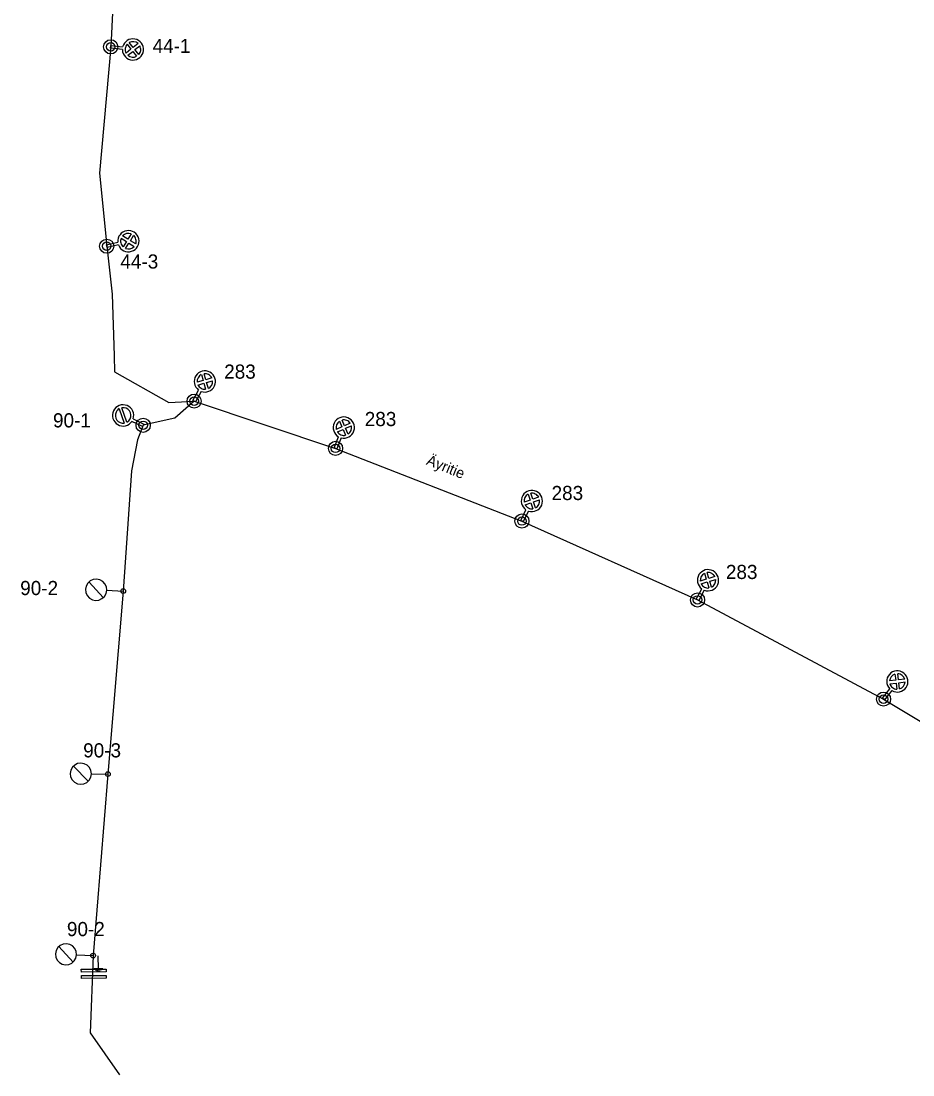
# Model space of a CAD drawing. Extents: x 25497851 to 25498523, y 6686544 to 6687372.
# Drawn here: x 25497924.4 to 25498113.5, y 6686887.2 to 6687110.6 of the extents above; entities that cross this region are included whole.
import ezdxf

# ---------------------------------------------------------------- set-up
doc = ezdxf.new("R2010")
doc.units = 0
for name, color, linetype in [('EL_CABLE_MAA', 7, 'Continuous'), ('KAAPELI', 7, 'Continuous'), ('KEYGWT_ANNOTATION', 7, 'Continuous'), ('Level 17', 7, 'Continuous'), ('Level 63', 7, 'Continuous'), ('MUU_UV-SUUNNITELMASYMBOLI', 7, 'Continuous'), ('PYLVAS', 7, 'Continuous'), ('Taso 1', 7, 'Continuous'), ('TEKSTI_SUUNNITELMA-ALUE', 7, 'Continuous'), ('VALAISIN', 7, 'Continuous')]:
    doc.layers.add(name, color=color, linetype=linetype)

msp = doc.modelspace()

# ---------------------------------------------------------------- linework, layer by layer
at = {"layer": 'EL_CABLE_MAA'}
for points in [[(25497946.1, 6686989.76), (25497942.85, 6686950.95)], [(25497942.85, 6686950.95), (25497939.72, 6686912.49)], [(25497939.72, 6686912.49), (25497939.1, 6686896.13), (25497945.31, 6686887.18)]]:
    msp.add_lwpolyline(points, dxfattribs=at)
at = {"layer": 'KAAPELI'}
for p, q in [((25497961.13, 6687030.03), (25497991.11, 6687020.01)), ((25497991.11, 6687020.01), (25498030.62, 6687004.6)), ((25498030.62, 6687004.6), (25498067.85, 6686987.87)), ((25498067.85, 6686987.87), (25498107.28, 6686966.85)), ((25498107.28, 6686966.85), (25498147.08, 6686942.96))]:
    msp.add_line(p, q, dxfattribs=at)
for points in [[(25497940.63, 6687135.56), (25497944.75, 6687131.17), (25497943.46, 6687105.16)], [(25497943.45, 6687105.13), (25497941.06, 6687078.34), (25497942.59, 6687062.85)], [(25497942.59, 6687062.86), (25497943.72, 6687052.67), (25497944.15, 6687039.66), (25497944.26, 6687036.24), (25497955.8, 6687029.73), (25497961.13, 6687030.03)], [(25497961.13, 6687030.03), (25497957.02, 6687026.41), (25497950.33, 6687024.9)], [(25497950.33, 6687024.9), (25497949.1, 6687021.84), (25497947.87, 6687015.26), (25497946.1, 6686989.76)]]:
    msp.add_lwpolyline(points, dxfattribs=at)
at = {"layer": 'Level 17'}
for points in [[(25497940.73, 6686912.4), (25497940.82, 6686909.68)], [(25497940.83, 6686909.67), (25497939.88, 6686909.64)], [(25497940.82, 6686909.42), (25497940.15, 6686909.4)], [(25497940.46, 6686909.14), (25497940.83, 6686909.15)], [(25497941.49, 6686909.44), (25497940.82, 6686909.42)], [(25497941.77, 6686909.7), (25497940.83, 6686909.67)], [(25497940.83, 6686909.15), (25497941.2, 6686909.17)]]:
    msp.add_lwpolyline(points, dxfattribs=at)
at = {"layer": 'MUU_UV-SUUNNITELMASYMBOLI'}
for p, q in [((25497937.21, 6686909.59), (25497942.46, 6686909.62)), ((25497937.22, 6686908.99), (25497937.21, 6686909.59)), ((25497942.47, 6686909.02), (25497937.22, 6686908.99)), ((25497942.46, 6686909.62), (25497942.47, 6686909.02)), ((25497937.22, 6686908.23), (25497942.47, 6686908.26)), ((25497937.23, 6686907.63), (25497937.22, 6686908.23)), ((25497942.48, 6686907.66), (25497937.23, 6686907.63)), ((25497942.47, 6686908.26), (25497942.48, 6686907.66))]:
    msp.add_line(p, q, dxfattribs=at)
at = {"layer": 'PYLVAS'}
for centre, radius in [((25497943.45, 6687105.13), 1.5), ((25497943.45, 6687105.13), 0.9), ((25497942.59, 6687062.86), 1.5), ((25497942.59, 6687062.86), 0.9), ((25497961.13, 6687030.03), 1.5), ((25497961.13, 6687030.03), 0.9), ((25497950.33, 6687024.9), 1.5), ((25497950.33, 6687024.9), 0.9), ((25497991.11, 6687020.01), 1.5), ((25497991.11, 6687020.01), 0.9), ((25498030.62, 6687004.6), 1.5), ((25498030.62, 6687004.6), 0.9), ((25498067.85, 6686987.87), 1.5), ((25498067.85, 6686987.87), 0.9), ((25498107.28, 6686966.85), 1.5), ((25498107.28, 6686966.85), 1.5), ((25498107.28, 6686966.85), 0.9), ((25498107.28, 6686966.85), 0.9)]:
    msp.add_circle(centre, radius, dxfattribs=at)
at = {"layer": 'Taso 1'}
for p, q in [((25497938.86, 6686991.67), (25497941.85, 6686988.39)), ((25497942.6, 6686989.92), (25497946.1, 6686989.76)), ((25497935.56, 6686952.63), (25497938.65, 6686949.44)), ((25497939.35, 6686951), (25497942.85, 6686950.95)), ((25497932.48, 6686914.4), (25497935.47, 6686911.11)), ((25497936.22, 6686912.65), (25497939.72, 6686912.49))]:
    msp.add_line(p, q, dxfattribs=at)
for points in [[(25497938.11, 6686990.14), (25497938.19, 6686989.44), (25497938.47, 6686988.79), (25497938.95, 6686988.27), (25497939.56, 6686987.92), (25497940.25, 6686987.78), (25497940.95, 6686987.86), (25497941.59, 6686988.15), (25497942.11, 6686988.62), (25497942.46, 6686989.23), (25497942.6, 6686989.92), (25497942.52, 6686990.62), (25497942.23, 6686991.27), (25497941.76, 6686991.79), (25497941.15, 6686992.13), (25497940.46, 6686992.28), (25497939.76, 6686992.2), (25497939.12, 6686991.91), (25497938.6, 6686991.44), (25497938.25, 6686990.82)], [(25497934.86, 6686951.07), (25497934.95, 6686950.37), (25497935.26, 6686949.74), (25497935.75, 6686949.24), (25497936.38, 6686948.91), (25497937.07, 6686948.79), (25497937.77, 6686948.89), (25497938.4, 6686949.2), (25497938.9, 6686949.69), (25497939.23, 6686950.31), (25497939.35, 6686951), (25497939.25, 6686951.7), (25497938.94, 6686952.33), (25497938.45, 6686952.84), (25497937.83, 6686953.16), (25497937.14, 6686953.29), (25497936.44, 6686953.19), (25497935.81, 6686952.88), (25497935.31, 6686952.39), (25497934.98, 6686951.76)], [(25497931.73, 6686912.86), (25497931.8, 6686912.16), (25497932.09, 6686911.52), (25497932.57, 6686911), (25497933.18, 6686910.65), (25497933.87, 6686910.51), (25497934.57, 6686910.59), (25497935.21, 6686910.88), (25497935.73, 6686911.35), (25497936.08, 6686911.96), (25497936.22, 6686912.65), (25497936.14, 6686913.35), (25497935.85, 6686913.99), (25497935.38, 6686914.51), (25497934.77, 6686914.86), (25497934.08, 6686915), (25497933.38, 6686914.93), (25497932.74, 6686914.64), (25497932.22, 6686914.16), (25497931.87, 6686913.55)]]:
    msp.add_lwpolyline(points, close=True, dxfattribs=at)
for centre in [(25497946.1, 6686989.76), (25497942.85, 6686950.95), (25497939.72, 6686912.49)]:
    msp.add_circle(centre, 0.5, dxfattribs=at)
at = {"layer": 'VALAISIN'}
for p, q in [((25497943.42, 6687104.83), (25497943.48, 6687105.43)), ((25497943.48, 6687105.43), (25497945.98, 6687105.14)), ((25497946.92, 6687105.67), (25497947.74, 6687104.63)), ((25497948.21, 6687105.01), (25497947.39, 6687106.04)), ((25497949.24, 6687105.83), (25497948.21, 6687105.01)), ((25497948.58, 6687104.54), (25497949.62, 6687105.36)), ((25497945.91, 6687104.54), (25497943.42, 6687104.83)), ((25497947.74, 6687104.63), (25497946.7, 6687103.81)), ((25497947.07, 6687103.34), (25497948.11, 6687104.16)), ((25497948.11, 6687104.16), (25497948.93, 6687103.13)), ((25497949.4, 6687103.5), (25497948.58, 6687104.54)), ((25497947.8, 6687065.48), (25497947.1, 6687064.36)), ((25497947.61, 6687064.04), (25497948.31, 6687065.16)), ((25497942.52, 6687063.15), (25497944.96, 6687063.72)), ((25497942.66, 6687062.56), (25497942.52, 6687063.15)), ((25497945.1, 6687063.14), (25497942.66, 6687062.56)), ((25497945.66, 6687064.54), (25497946.79, 6687063.84)), ((25497947.1, 6687064.36), (25497945.98, 6687065.05)), ((25497946.79, 6687063.84), (25497946.09, 6687062.72)), ((25497946.6, 6687062.4), (25497947.3, 6687063.53)), ((25497947.3, 6687063.53), (25497948.42, 6687062.83)), ((25497948.74, 6687063.34), (25497947.61, 6687064.04)), ((25497963.03, 6687034.39), (25497961.76, 6687034.02)), ((25497962.66, 6687035.66), (25497963.03, 6687034.39)), ((25497963.61, 6687034.56), (25497963.23, 6687035.83)), ((25497964.88, 6687034.93), (25497963.61, 6687034.56)), ((25497963.78, 6687033.98), (25497965.04, 6687034.36)), ((25497964.15, 6687032.71), (25497963.78, 6687033.98)), ((25497960.87, 6687030.17), (25497962.07, 6687032.37)), ((25497962.6, 6687032.09), (25497961.39, 6687029.88)), ((25497961.93, 6687033.44), (25497963.2, 6687033.82)), ((25497963.2, 6687033.82), (25497963.57, 6687032.55)), ((25497961.39, 6687029.88), (25497960.87, 6687030.17)), ((25497945.27, 6687028.42), (25497946.31, 6687025.35)), ((25497946.88, 6687025.55), (25497945.83, 6687028.62)), ((25497950.2, 6687024.63), (25497947.94, 6687025.73)), ((25497948.21, 6687026.27), (25497950.46, 6687025.17)), ((25497950.46, 6687025.17), (25497950.2, 6687024.63)), ((25497991.94, 6687025.78), (25497992.46, 6687024.57)), ((25497993.01, 6687024.81), (25497992.49, 6687026.02)), ((25497994.23, 6687025.33), (25497993.01, 6687024.81)), ((25497992.46, 6687024.57), (25497991.25, 6687024.04)), ((25497991.49, 6687023.49), (25497992.7, 6687024.02)), ((25497992.7, 6687024.02), (25497993.23, 6687022.81)), ((25497993.25, 6687024.26), (25497994.46, 6687024.78)), ((25497993.78, 6687023.04), (25497993.25, 6687024.26)), ((25497990.83, 6687020.12), (25497991.76, 6687022.45)), ((25497992.31, 6687022.23), (25497991.39, 6687019.9)), ((25497991.39, 6687019.9), (25497990.83, 6687020.12)), ((25498031.92, 6687010.29), (25498032.35, 6687009.04)), ((25498032.91, 6687009.23), (25498032.49, 6687010.48)), ((25498034.17, 6687009.65), (25498032.91, 6687009.23)), ((25498032.35, 6687009.04), (25498031.09, 6687008.61)), ((25498031.29, 6687008.04), (25498032.54, 6687008.47)), ((25498032.54, 6687008.47), (25498032.96, 6687007.21)), ((25498033.11, 6687008.66), (25498034.36, 6687009.08)), ((25498033.53, 6687007.41), (25498033.11, 6687008.66)), ((25498030.36, 6687004.73), (25498031.47, 6687006.98)), ((25498032.01, 6687006.72), (25498030.89, 6687004.47)), ((25498030.89, 6687004.47), (25498030.36, 6687004.73)), ((25498070.27, 6686992.43), (25498069.89, 6686993.69)), ((25498069.7, 6686992.25), (25498068.44, 6686991.87)), ((25498068.61, 6686991.29), (25498069.88, 6686991.68)), ((25498069.32, 6686993.52), (25498069.7, 6686992.25)), ((25498069.88, 6686991.68), (25498070.26, 6686990.41)), ((25498071.54, 6686992.81), (25498070.27, 6686992.43)), ((25498070.45, 6686991.85), (25498071.71, 6686992.24)), ((25498070.83, 6686990.59), (25498070.45, 6686991.85)), ((25498067.58, 6686988.01), (25498068.76, 6686990.23)), ((25498069.29, 6686989.95), (25498068.11, 6686987.73)), ((25498068.11, 6686987.73), (25498067.58, 6686988.01)), ((25498109.71, 6686972.16), (25498109.87, 6686970.85)), ((25498110.46, 6686970.92), (25498110.3, 6686972.24)), ((25498109.87, 6686970.85), (25498108.56, 6686970.69)), ((25498108.63, 6686970.09), (25498109.94, 6686970.25)), ((25498109.94, 6686970.25), (25498110.1, 6686968.94)), ((25498111.78, 6686971.08), (25498110.46, 6686970.92)), ((25498110.54, 6686970.33), (25498111.85, 6686970.49)), ((25498110.7, 6686969.02), (25498110.54, 6686970.33)), ((25498107.05, 6686967.04), (25498108.59, 6686969.02)), ((25498107.52, 6686966.67), (25498107.05, 6686967.04)), ((25498109.07, 6686968.65), (25498107.52, 6686966.67))]:
    msp.add_line(p, q, dxfattribs=at)
for centre, radius, start, end in [((25497948.16, 6687104.58), 2.25, 353.4004, 165.7381), ((25497948.16, 6687104.58), 1.65, 138.876, 173.4004), ((25497948.16, 6687104.58), 1.65, 48.876, 117.9247), ((25497948.16, 6687104.58), 1.65, 353.4004, 27.9247), ((25497948.16, 6687104.58), 2.25, 181.0626, 353.4004), ((25497948.16, 6687104.58), 1.65, 173.4004, 207.9247), ((25497948.16, 6687104.58), 1.65, 228.876, 297.9247), ((25497948.16, 6687104.58), 1.65, 318.876, 353.4004), ((25497947.2, 6687063.94), 2.25, 13.2418, 185.5795), ((25497947.2, 6687063.94), 1.65, 68.7175, 137.7661), ((25497947.2, 6687063.94), 1.65, 13.2418, 47.7661), ((25497947.2, 6687063.94), 2.25, 200.904, 13.2418), ((25497947.2, 6687063.94), 1.65, 158.7175, 193.2418), ((25497947.2, 6687063.94), 1.65, 193.2418, 227.7661), ((25497947.2, 6687063.94), 1.65, 338.7175, 13.2418), ((25497947.2, 6687063.94), 1.65, 248.7175, 317.7661), ((25497963.4, 6687034.19), 2.25, 61.3434, 233.6812), ((25497963.4, 6687034.19), 2.25, 249.0057, 61.3434), ((25497963.4, 6687034.19), 1.65, 116.8191, 185.8678), ((25497963.4, 6687034.19), 1.65, 61.3434, 95.8678), ((25497963.4, 6687034.19), 1.65, 296.8191, 5.8678), ((25497963.4, 6687034.19), 1.65, 26.8191, 61.3434), ((25497963.4, 6687034.19), 1.65, 206.8191, 241.3434), ((25497963.4, 6687034.19), 1.65, 241.3434, 275.8678), ((25497946.07, 6687026.99), 2.25, 153.8595, 326.1972), ((25497946.07, 6687026.99), 2.25, 341.5217, 153.8595), ((25497946.07, 6687026.99), 1.65, 153.8595, 278.3838), ((25497946.07, 6687026.99), 1.65, 119.3352, 153.8595), ((25497946.07, 6687026.99), 1.65, 333.8595, 98.3838), ((25497946.07, 6687026.99), 1.65, 299.3352, 333.8595), ((25497992.86, 6687024.41), 2.25, 68.4031, 240.7408), ((25497992.86, 6687024.41), 1.65, 123.8788, 192.9274), ((25497992.86, 6687024.41), 2.25, 256.0653, 68.4031), ((25497992.86, 6687024.41), 1.65, 68.4031, 102.9274), ((25497992.86, 6687024.41), 1.65, 33.8788, 68.4031), ((25497992.86, 6687024.41), 1.65, 213.8788, 248.4031), ((25497992.86, 6687024.41), 1.65, 248.4031, 282.9274), ((25497992.86, 6687024.41), 1.65, 303.8788, 12.9274), ((25498032.73, 6687008.85), 2.25, 63.6694, 236.0071), ((25498032.73, 6687008.85), 1.65, 119.145, 188.1937), ((25498032.73, 6687008.85), 2.25, 251.3316, 63.6694), ((25498032.73, 6687008.85), 1.65, 63.6694, 98.1937), ((25498032.73, 6687008.85), 1.65, 29.145, 63.6694), ((25498032.73, 6687008.85), 1.65, 209.145, 243.6694), ((25498032.73, 6687008.85), 1.65, 243.6694, 278.1937), ((25498032.73, 6687008.85), 1.65, 299.145, 8.1937), ((25498070.07, 6686992.05), 2.25, 61.9449, 234.2826), ((25498070.07, 6686992.05), 2.25, 249.6071, 61.9449), ((25498070.07, 6686992.05), 1.65, 61.9449, 96.4692), ((25498070.07, 6686992.05), 1.65, 117.4206, 186.4692), ((25498070.07, 6686992.05), 1.65, 297.4206, 6.4692), ((25498070.07, 6686992.05), 1.65, 27.4206, 61.9449), ((25498070.07, 6686992.05), 1.65, 207.4206, 241.9449), ((25498070.07, 6686992.05), 1.65, 241.9449, 276.4692), ((25498110.2, 6686970.59), 2.25, 52.004, 224.3417), ((25498110.2, 6686970.59), 1.65, 107.4797, 176.5283), ((25498110.2, 6686970.59), 2.25, 239.6662, 52.004), ((25498110.2, 6686970.59), 1.65, 52.004, 86.5283), ((25498110.2, 6686970.59), 1.65, 17.4797, 52.004), ((25498110.2, 6686970.59), 1.65, 197.4797, 232.004), ((25498110.2, 6686970.59), 1.65, 232.004, 266.5283), ((25498110.2, 6686970.59), 1.65, 287.4797, 356.5283)]:
    msp.add_arc(centre, radius, start, end, dxfattribs=at)

# ---------------------------------------------------------------- texts
at = {"layer": 'KEYGWT_ANNOTATION'}
for s, p in [('44-1', (25497952.33, 6687103.83)), ('44-3', (25497945.49, 6687058.13)), ('283', (25497967.5, 6687034.78)), ('90-1', (25497931.21, 6687024.45)), ('283', (25497997.3, 6687024.73)), ('283', (25498036.91, 6687009.05)), ('283', (25498073.86, 6686992.31)), ('90-2', (25497924.26, 6686988.9)), ('90-3', (25497937.61, 6686954.49)), ('90-2', (25497934.16, 6686916.6))]:
    msp.add_text(s, height=3, dxfattribs=at).set_placement(p)
at = {"layer": 'Level 63'}
msp.add_text('(C) KEYPRO 2000', height=0.0001, rotation=1.8, dxfattribs=at).set_placement((25497940.46, 6686909.14))
at = {"layer": 'TEKSTI_SUUNNITELMA-ALUE'}
msp.add_text('Äyritie', height=2.25, rotation=337.8755, dxfattribs=at).set_placement((25498010.19, 6687016.64))

doc.saveas('drawing.dxf')
